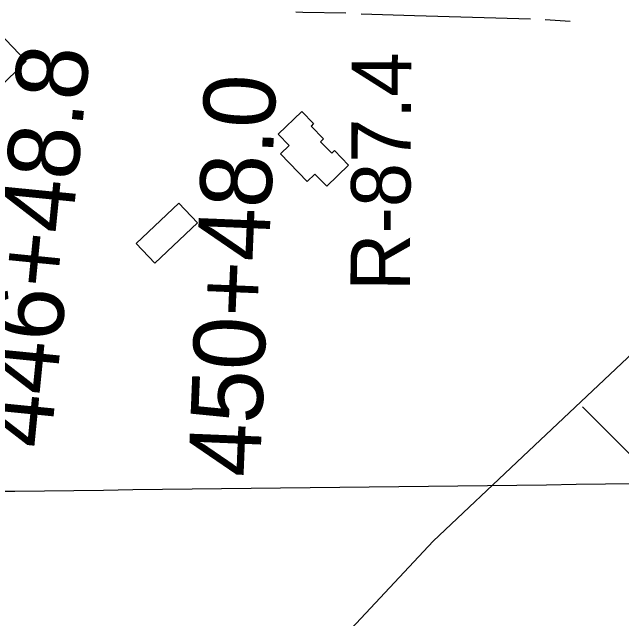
# Model space of a CAD drawing. Extents: x 3704301 to 3742427, y 506229 to 532009.
# Drawn here: x 3717817 to 3718668, y 517639 to 518486 of the extents above; entities that cross this region are included whole.
import ezdxf

# ---------------------------------------------------------------- set-up
doc = ezdxf.new("R2010")
doc.units = 0
for name, color, linetype in [('V-BLDG-OTLN', 7, 'Continuous'), ('V-GRID-MAJR', 7, 'Continuous'), ('V-RIVR-RANG-IDEN', 7, 'Continuous'), ('V-SITE-VEGE', 7, 'Continuous'), ('V-SURV-IDEN', 7, 'Continuous'), ('V-TOPO-SHOR', 7, 'Continuous')]:
    doc.layers.add(name, color=color, linetype=linetype)

msp = doc.modelspace()

# ---------------------------------------------------------------- linework, layer by layer
at = {"layer": 'V-BLDG-OTLN'}
for points in [[(3717836.242, 518418.021), (3717795.717, 518378.655), (3717770.108, 518405.017), (3717743.792, 518379.451), (3717724.415, 518399.39900000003), (3717750.202, 518424.44800000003), (3717756.518, 518417.94800000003), (3717797.5840000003, 518457.814)], [(3718286.3910000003, 518273.015), (3718255.794, 518243.39), (3718239.311, 518260.413), (3718228.586, 518250.028), (3718191.208, 518288.63300000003), (3718203.3910000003, 518300.427), (3718188.103, 518316.217), (3718220.849, 518347.922), (3718237.444, 518330.77900000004), (3718233.954, 518327.39900000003), (3718251.3540000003, 518309.43), (3718247.3310000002, 518305.537), (3718262.855, 518289.503), (3718266.767, 518293.284)], [(3717989.826, 518163.598), (3718049.183, 518219.853), (3718075.307, 518192.289), (3718015.948, 518136.034)]]:
    msp.add_lwpolyline(points, close=True, dxfattribs=at)
at = {"layer": 'V-GRID-MAJR'}
msp.add_spline([(3708498.534, 517706.704), (3713778.102, 517769.291), (3719057.661, 517832.646), (3724337.211, 517896.76900000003), (3729616.752, 517961.659), (3734896.2830000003, 518027.318), (3740175.804, 518093.744), (3740175.805, 518093.744)], degree=3, dxfattribs=at)
at = {"layer": 'V-SITE-VEGE'}
msp.add_lwpolyline([(3718262.986, 517596.517), (3718404.3310000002, 517747.742), (3718529.615, 517866.21400000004), (3718732.7830000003, 518057.346)], dxfattribs=at)
at = {"layer": 'V-TOPO-SHOR'}
msp.add_line((3718595.751, 518473.211), (3718560.716, 518475.53500000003), dxfattribs=at)
for points in [[(3718282.6240000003, 518484.909), (3718222.626, 518485.96), (3718212.665, 518486.398)], [(3718540.519, 518476.55100000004), (3718378.413, 518481.458), (3718304.128, 518483.674)], [(3718613.165, 517935.193), (3719001.931, 517545.815), (3719357.216, 517193.594)]]:
    msp.add_lwpolyline(points, dxfattribs=at)

# ---------------------------------------------------------------- texts
at = {"layer": 'V-RIVR-RANG-IDEN'}
msp.add_text('R-87.4', height=82.99999799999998, rotation=89.63814097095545, dxfattribs=at).set_placement((3718371.860252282, 518096.8983973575))
at = {"layer": 'V-SURV-IDEN'}
for s, height, rotation, p in [('446+48.8', 99.99999999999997, 84.33563635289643, (3717869.86738652, 517875.8436641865)), ('450+48.0', 100, 87.6316666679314, (3718162.1981185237, 517836.35729299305))]:
    msp.add_text(s, height=height, rotation=rotation, dxfattribs=at).set_placement(p)

doc.saveas('drawing.dxf')
